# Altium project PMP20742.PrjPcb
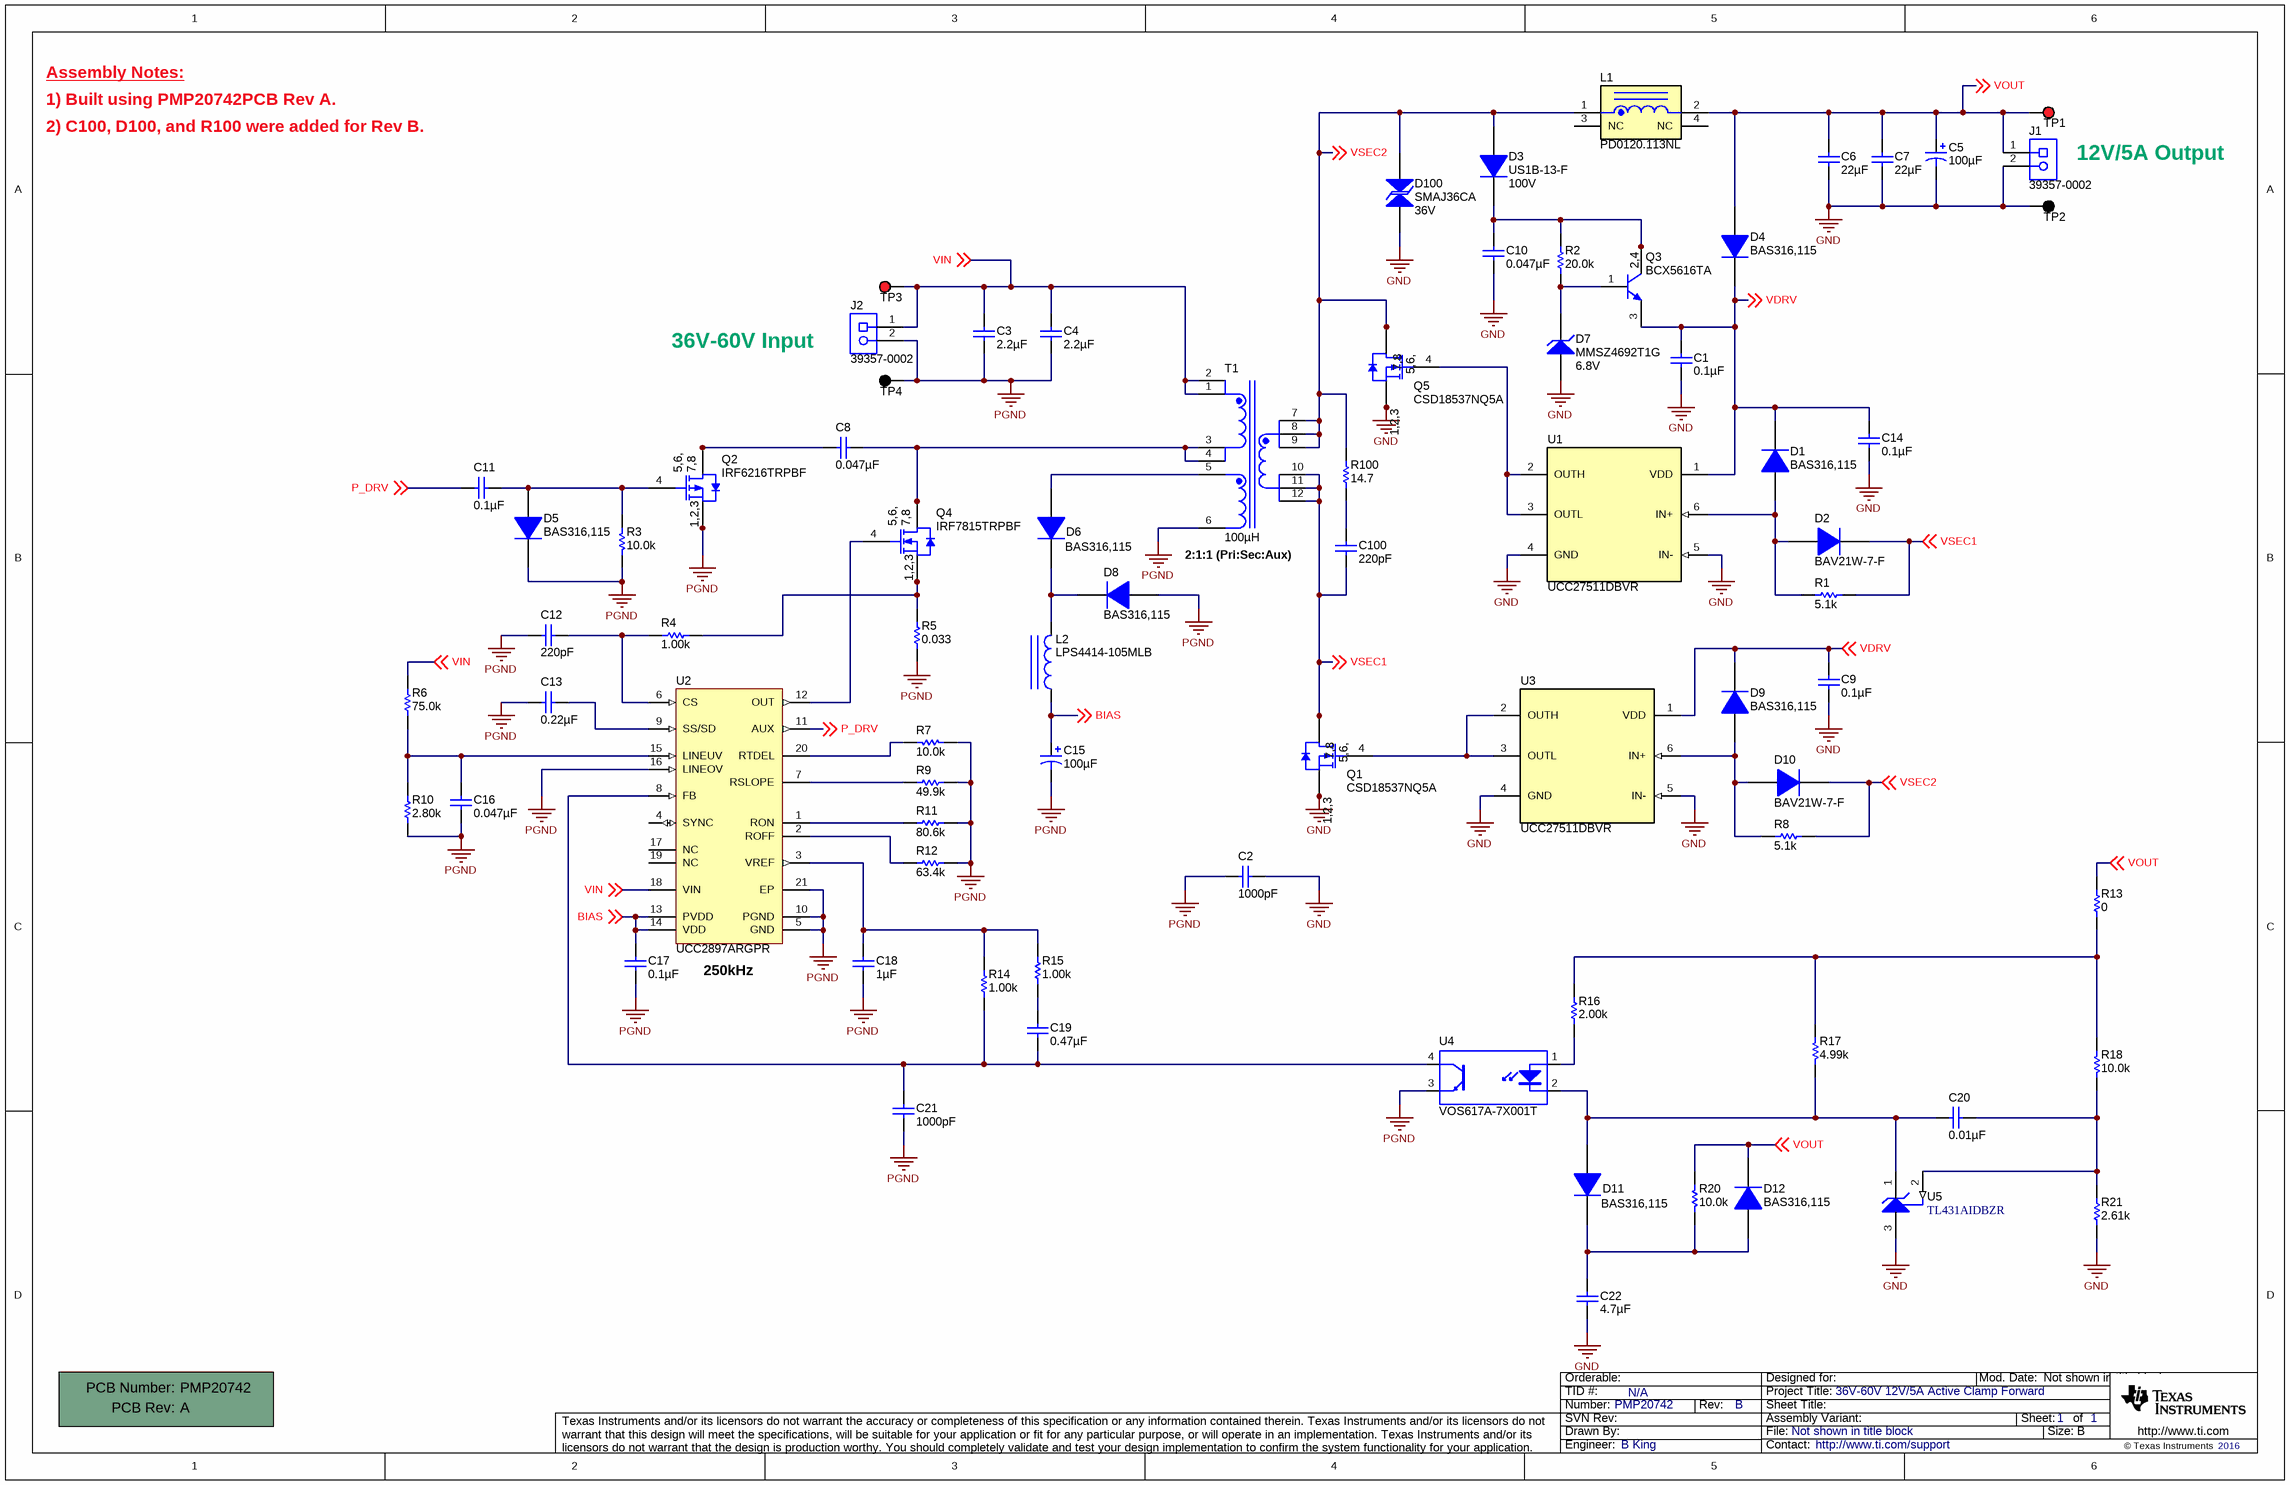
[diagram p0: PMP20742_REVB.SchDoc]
TID: N/A; TechSupport: http://www.ti.com/support; SCH_Rev: B; PRJ_Title: 36V-60V 12V/5A Active Clamp Forward; PRJ_Number: PMP20742; PRJ_Engineer: B King; PCB_Rev: A; PCB_Layout: B King; CopyrightYear: 2016
1 sheet, 77 parts. Net scope: global (net labels, ports and power ports of the same name join across sheets).
Board file: PMP20742_REVA.PcbDoc

## Sheet PMP20742_REVB.SchDoc
size 431 x 279 mm; Date: Not shown in title block; ApprovedBy: Not shown in title block; CheckedBy: Not shown in title block; Author: Not shown in title block; CompanyName: Not shown in title block; Engineer: Not shown in title block; Organization: Not shown in title block; Address1: Not shown in title block; Address2: Not shown in title block; Address3: Not shown in title block; Address4: Not shown in title block; DocumentNumber: 1; Revision: Use project parameter SCH_Rev; SheetNumber: 1; SheetTotal: 1; PageSetup: Record=PageOptions¦CenterHorizontal=True¦CenterVertical=True¦PrintScale=1.00¦XCorrection=1.00¦YCorrection=1.00¦PrintKind=0¦BorderSize=5000000¦LeftOffset=0¦BottomOffset=0¦Orientation=2¦PaperLength=1000¦PaperWidth=1000¦Scale=100¦PaperSource=15¦PrintQuality=600¦MediaType=1¦DitherType=10¦PaperKind=Letter¦PrintScaleMode=1

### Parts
!PCB1  Printed Circuit Board  (value not drawn)  (mechanical)
C1  ValueDisplayed: 0.1µF  [0402L]  (hidden comment: GRM155R71E104KE14D)
C2  ValueDisplayed: 1000pF  [1808_L]  (hidden comment: STD)
C3  ValueDisplayed: 2.2µF  [1210_270L]  (hidden comment: GRM32ER72A225KA35L)
C4  ValueDisplayed: 2.2µF  [1210_270L]  (hidden comment: GRM32ER72A225KA35L)
C5  ValueDisplayed: 100µF  [SM_RADIAL_6.3BMM]  (hidden comment: EEHZA1E101XP)
C6  ValueDisplayed: 22µF  [1206_190L]  (hidden comment: GRM31CC81E226ME11L)
C7  ValueDisplayed: 22µF  [1206_190L]  (hidden comment: GRM31CC81E226ME11L)
C8  ValueDisplayed: 0.047µF  [1206_180L]  (hidden comment: GRM31CR72E473KW03L)
C9  ValueDisplayed: 0.1µF  [0402L]  (hidden comment: GRM155R71E104KE14D)
C10  ValueDisplayed: 0.047µF  [0805L]  (hidden comment: GRM21BR72A473KA01L)
C11  ValueDisplayed: 0.1µF  [0402L]  (hidden comment: GRM155R71E104KE14D)
C12  ValueDisplayed: 220pF  [0402L]  (hidden comment: GRM1555C1H221JA01D)
C13  ValueDisplayed: 0.22µF  [0402L]  (hidden comment: GRM155R61A224KE19D)
C14  ValueDisplayed: 0.1µF  [0402L]  (hidden comment: GRM155R71E104KE14D)
C15  ValueDisplayed: 100µF  [SM_RADIAL_6.3BMM]  (hidden comment: EEHZA1E101XP)
C16  ValueDisplayed: 0.047µF  [0402L]  (hidden comment: GRM155R71E473KA88D)
C17  ValueDisplayed: 0.1µF  [0402L]  (hidden comment: GRM155R71E104KE14D)
C18  ValueDisplayed: 1µF  [0402L]  (hidden comment: GRM155R61A105KE15D)
C19  ValueDisplayed: 0.47µF  [0402L]  (hidden comment: GRM155R61C474KE01)
C20  ValueDisplayed: 0.01µF  [0402L]  (hidden comment: GRM155R71E103KA01D)
C21  ValueDisplayed: 1000pF  [0402L]  (hidden comment: GRM155R61H102KA01D)
C22  ValueDisplayed: 4.7µF  [0805L]  (hidden comment: GRM21BR71E475KA73L)
C100  ValueDisplayed: 220pF  [0603L]  (hidden comment: GRM188R72A221KA01D)
D1  BAS316,115  [sod-323]
D2  BAV21W-7-F  [SOD-123]
D3  US1B-13-F  value 100V  [SMA]
D4  BAS316,115  [sod-323]
D5  BAS316,115  [sod-323]
D6  BAS316,115  [sod-323]
D7  MMSZ4692T1G  value 6.8V  [SOD-123]
D8  BAS316,115  [sod-323]
D9  BAS316,115  [sod-323]
D10  BAV21W-7-F  [SOD-123]
D11  BAS316,115  [sod-323]
D12  BAS316,115  [sod-323]
D100  SMAJ36CA  value 36V  [SMA]
J1  39357-0002  [Molex_39357-0002]
J2  39357-0002  [Molex_39357-0002]
L1  PD0120.113NL  [PD0120NL]
L2  LPS4414-105MLB  [LPS4414]
Q1  CSD18537NQ5A  [DQJ0008A]
Q2  IRF6216TRPBF  [SOIC-8L]
Q3  BCX5616TA  [SOT-89-3]
Q4  IRF7815TRPBF  [SO-8L]
Q5  CSD18537NQ5A  [DQJ0008A]
R1  value 5.1k  [0805L]  (hidden comment: CRCW08055K10JNEA)
R2  value 20.0k  [0805L]  (hidden comment: CRCW080520K0FKEA)
R3  value 10.0k  [0402L]  (hidden comment: CRCW040210K0FKED)
R4  value 1.00k  [0402L]  (hidden comment: CRCW04021K00FKED)
R5  ValueDisplayed: 0.033  [1206L]  (hidden comment: ERJ-8CWFR033V)
R6  ValueDisplayed: 75.0k  [0402L]  (hidden comment: CRCW040275K0FKED)
R7  value 10.0k  [0402L]  (hidden comment: CRCW040210K0FKED)
R8  value 5.1k  [0805L]  (hidden comment: CRCW08055K10JNEA)
R9  ValueDisplayed: 49.9k  [0402L]  (hidden comment: CRCW040249K9FKED)
R10  ValueDisplayed: 2.80k  [0402L]  (hidden comment: CRCW04022K80FKED)
R11  ValueDisplayed: 80.6k  [0402L]  (hidden comment: CRCW040280K6FKED)
R12  ValueDisplayed: 63.4k  [0402L]  (hidden comment: CRCW040263K4FKED)
R13  value 0  [0402L]  (hidden comment: CRCW04020000Z0ED)
R14  value 1.00k  [0402L]  (hidden comment: CRCW04021K00FKED)
R15  value 1.00k  [0402L]  (hidden comment: CRCW04021K00FKED)
R16  value 2.00k  [0402L]  (hidden comment: CRCW04022K00FKED)
R17  value 4.99k  [0402L]  (hidden comment: CRCW04024K99FKED)
R18  value 10.0k  [0402L]  (hidden comment: CRCW040210K0FKED)
R20  value 10.0k  [0402L]  (hidden comment: CRCW040210K0FKED)
R21  value 2.61k  [0402L]  (hidden comment: CRCW04022K61FKED)
R100  ValueDisplayed: 14.7  [1206L]  (hidden comment: CRCW120614R7FKEA)
T1  ValueDisplayed: 100µH  [Pulse_PA2398NL]  (hidden comment: PA2398NL)
TP1  5000  [Keystone5000]  (value not drawn)
TP2  5001  [Keystone5001]  (value not drawn)
TP3  5000  [Keystone5000]  (value not drawn)
TP4  5001  [Keystone5001]  (value not drawn)
U1  UCC27511DBVR  [DBV0006A_L]
U2  UCC2897ARGPR  [RGP0020D]
U3  UCC27511DBVR  [DBV0006A_L]
U4  VOS617A-7X001T  [SSOP-4_VISHAY]
U5  TL431AIDBZR  [DBZ0003A_L]

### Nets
GND: C1.2 C2.1 C5.2(-) C6.2 C7.2 C9.2 C10.2 C14.2 C22.2 D7.2(A) D100.1 J1.2 Q1.1(S) Q1.2(S) Q1.3(S) Q5.1(S) Q5.2(S) Q5.3(S) R21.1 TP2.1 U1.4(GND) U1.5(IN-) U3.4(GND) U3.5(IN-) U5.3(ANODE)
PGND: C2.2 C3.2 C4.2 C12.1 C13.1 C15.2(-) C16.1 C17.2 C18.2 C21.2 D5.1(K) D8.2(A) J2.2 Q2.1(S) Q2.2(S) Q2.3(S) R3.1 R5.1 R7.1 R9.1 R10.1 R11.1 R12.1 T1.6 TP4.1 U2.5(GND) U2.10(PGND) U2.16(LINEOV) U2.21(EP) U4.3(E)
BIAS: C15.1(+) C17.1 L2.1 U2.13(PVDD) U2.14(VDD) ; off-sheet BIAS
P_DRV: C11.1 U2.11(AUX) ; off-sheet P_DRV
VDRV: C1.1 C9.1 C14.1 D1.1(K) D4.1(K) D9.1(K) Q3.3(E) U1.1(VDD) U3.1(VDD) ; off-sheet VDRV
VIN: C3.1 C4.1 J2.1 R6.2 T1.1 T1.2 TP3.1 U2.18(VIN) ; off-sheet VIN
VOUT: C5.1(+) C6.1 C7.1 D4.2(A) D12.1(K) J1.1 L1.2 R13.2 R20.2 TP1.1 ; off-sheet VOUT
VSEC1: C100.2 D2.1(K) Q1.5(D) Q1.6(D) Q1.7(D) Q1.8(D) Q1.9(D) R1.1 T1.10 T1.11 T1.12 ; off-sheet VSEC1
VSEC2: D3.2(A) D10.1(K) D100.2 L1.1 Q5.5(D) Q5.6(D) Q5.7(D) Q5.8(D) Q5.9(D) R8.1 R100.2 T1.7 T1.8 T1.9 ; off-sheet VSEC2
NetC8_1: C8.1 Q2.5(D) Q2.6(D) Q2.7(D) Q2.8(D)
NetC8_2: C8.2 Q4.5(D) Q4.6(D) Q4.7(D) Q4.8(D) T1.3 T1.4
NetC10_1: C10.1 D3.1(K) Q3.2(C) Q3.4(C) R2.2
NetC11_2: C11.2 D5.2(A) Q2.4(G) R3.2
NetC12_2: C12.2 R4.2 U2.6(CS)
NetC13_2: C13.2 U2.9(SS/SD)
NetC16_2: C16.2 R6.1 R10.2 U2.15(LINEUV)
NetC18_1: C18.1 R14.1 R15.1 U2.3(VREF)
NetC19_1: C19.1 R15.2
NetC19_2: C19.2 C21.1 R14.2 U2.8(FB) U4.4(C)
NetC20_1: C20.1 R18.1 R21.2 U5.2(REF)
NetC20_2: C20.2 D11.2(A) R17.1 U4.2(K) U5.1(CATHODE)
NetC22_1: C22.1 D11.1(K) D12.2(A) R20.1
NetC100_1: C100.1 R100.1
NetD1_2: D1.2(A) D2.2(A) R1.2 U1.6(IN+)
NetD6_1: D6.1(K) D8.1(K) L2.2
NetD6_2: D6.2(A) T1.5
NetD7_1: D7.1(K) Q3.1(B) R2.1
NetD9_2: D9.2(A) D10.2(A) R8.2 U3.6(IN+)
NetQ1_4: Q1.4(G) U3.2(OUTH) U3.3(OUTL)
NetQ4_1: Q4.1(S) Q4.2(S) Q4.3(S) R4.1 R5.2
NetQ4_4: Q4.4(G) U2.12(OUT)
NetQ5_4: Q5.4(G) U1.2(OUTH) U1.3(OUTL)
NetR7_2: R7.2 U2.20(RTDEL)
NetR9_2: R9.2 U2.7(RSLOPE)
NetR11_2: R11.2 U2.1(RON)
NetR12_2: R12.2 U2.2(ROFF)
NetR13_1: R13.1 R16.2 R17.2 R18.2
NetR16_1: R16.1 U4.1(A)

Not connected (* = marked no-connect by the designer): L1 3(NC) 4(NC); U2 4(SYNC) 17(NC) 19(NC)

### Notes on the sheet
- Assembly Notes:
- 1) Built using PMP20742PCB Rev A.
- 2) C100, D100, and R100 were added for Rev B.
- 12V/5A Output
- 36V-60V Input
- (near T1) 2:1:1 (Pri:Sec:Aux)
- (near U2) 250kHz

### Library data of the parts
!PCB1 = PCB: Manufacturer: Any; PartNumber: PMP20742; SymbolCreator: a0412235
C1 C9 C11 C14 C17 = GRM155R71E104KE14D: CAP, CERM, 0.1 µF, 25 V, +/- 10%, X7R, 0402; Manufacturer: MuRata; Polarized: N; CompType: Capacitor; Value: 0.1uF; U/M: EA; Cap_F: 0.0000001; Tolerance_%: 10; Value1: Unknown; VDC_V: 25; Value2: 25V; TaMin_C: -55; TaMax_C: 125; Cap_Case: 0402; SizeArea_mm2: 0.5; SizeAreaWB_mm2: 3; SizeX_mm: 1; SizeZ_mm: 0.6; AEC Category: Q200
C2 = VJ1808Y102KXEAT5Z: CAP, CERM, 1000pF, 3kV, 1808; Polarized: N; CompType: Capacitor; U/M: EA; Cap_F: 0.000000001; Tolerance_%: 10; Value1: Unknown; TempCo: X7R; TaMin_C: -55; TaMax_C: 125; Cap_Case: 1808
C3 C4 = GRM32ER72A225KA35L: CAP, CERM, 2.2 µF, 100 V, +/- 10%, X7R, 1210; Manufacturer: MuRata; Polarized: N; CompType: Capacitor; Value: 2.2uF; U/M: EA; Cap_F: 0.0000022; Tolerance_%: 10; ESR_ohm: 0.007; Value1: 0.007 ohm; VDC_V: 100; Value2: 100V; IRMS_A: 4.4; TaMin_C: -55; TaMax_C: 125; Cap_Case: 1210; SizeArea_mm2: 8; SizeAreaWB_mm2: 14.7; SizeX_mm: 3.2; SizeY_mm: 2.5; SizeZ_mm: 2.7; AEC Category: Q200
C5 C15 = EEHZA1E101XP: CAP, Polymer Hybrid, 100 µF, 25 V, +/- 20%, 30 ohm, 6.3x7.7 SMD; Manufacturer: Panasonic; Polarized: Y; CompType: Capacitor; Value: 100uF; U/M: EA; Cap_F: 0.0001; Tolerance_%: 20; Value1: 30 ohm; VDC_V: 25; Value2: 25V; ESR_ohm: 30; IRMS_A: 2; TaMin_C: -55; TaMax_C: 105; SizeAreaWB_mm2: 79.98; SizeArea_mm2: 48.18; SizeX_mm: 7.3; SizeY_mm: 6.6; SizeZ_mm: 7.7; AEC Category: Q200
C6 C7 = GRM31CC81E226ME11L: CAP, CERM, 22 µF, 25 V, +/- 20%, X6S, 1206_190; Manufacturer: MuRata; Polarized: N; CompType: Capacitor; Value: 22uF; U/M: EA; Cap_F: 0.000022; Tolerance_%: 20; Value1: Unknown; VDC_V: 25; Value2: 25V; TaMin_C: -55; TaMax_C: 105; Cap_Case: 1206; SizeArea_mm2: 5.12; SizeAreaWB_mm2: 10.92; SizeX_mm: 3.2; SizeY_mm: 1.6; SizeZ_mm: 1.9; AEC Category: Q200
C8 = GRM31CR72E473KW03L: CAP, CERM, 0.047 µF, 250 V, +/- 10%, X7R, 1206; Manufacturer: MuRata; Polarized: N; CompType: Capacitor; Value: 0.047uF; U/M: EA; Cap_F: 0.000000047; Tolerance_%: 10; Value1: Unknown; VDC_V: 250; Value2: 250V; TaMin_C: -55; TaMax_C: 125; Cap_Case: 1206; SizeArea_mm2: 5.12; SizeAreaWB_mm2: 10.92; SizeX_mm: 3.2; SizeY_mm: 1.6; SizeZ_mm: 1.8; AEC Category: Q200
C10 = GRM21BR72A473KA01L: CAP, CERM, 0.047 µF, 100 V, +/- 10%, X7R, 0805; Manufacturer: MuRata; Polarized: N; CompType: Capacitor; Value: 0.047uF; U/M: EA; Cap_F: 0.000000047; Tolerance_%: 10; Value1: Unknown; VDC_V: 100; Value2: 100V; TaMin_C: -55; TaMax_C: 125; Cap_Case: 0805; SizeArea_mm2: 2.5; SizeAreaWB_mm2: 6.75; SizeX_mm: 2; SizeY_mm: 1.25; SizeZ_mm: 1.45; AEC Category: Q200
C12 = GRM1555C1H221JA01D: CAP, CERM, 220 pF, 50 V, +/- 5%, C0G/NP0, 0402; Manufacturer: MuRata; Polarized: N; CompType: Capacitor; Value: 220pF; U/M: EA; Cap_F: 0.00000000022; Tolerance_%: 5; Value1: Unknown; VDC_V: 50; Value2: 50V; TaMin_C: -55; TaMax_C: 125; Cap_Case: 0402; SizeArea_mm2: 0.5; SizeAreaWB_mm2: 3; SizeX_mm: 1; SizeZ_mm: 0.6; AEC Category: Q200
C13 = GRM155R61A224KE19D: CAP, CERM, 0.22uF, 10V, +/-10%, X5R, 0402; Manufacturer: MuRata; Polarized: N; CompType: Capacitor; U/M: EA; Cap_F: 0.00000022; Tolerance_%: 10; Value1: Unknown; TaMin_C: -55; TaMax_C: 85; Cap_Case: 0402
C16 = GRM155R71E473KA88D: CAP, CERM, 0.047uF, 25V, +/-10%, X7R, 0402; Manufacturer: MuRata; Polarized: N; CompType: Capacitor; U/M: EA; Cap_F: 0.000000047; Tolerance_%: 10; Value1: Unknown; VDC_V: 25; TaMin_C: -55; TaMax_C: 125; Cap_Case: 0402
C18 = GRM155R61A105KE15D: CAP, CERM, 1uF, 10V, +/-10%, X5R, 0402; Manufacturer: MuRata; Polarized: N; CompType: Capacitor; U/M: EA; Cap_F: 0.000001; Tolerance_%: 10; Value1: Unknown; TaMin_C: -55; TaMax_C: 85; Cap_Case: 0402
C19 = GRM155R61C474KE01: CAP, CERM, 0.47 µF, 16 V, +/- 10%, X5R, 0402; Manufacturer: MuRata; Polarized: N; CompType: Capacitor; Value: 0.47uF; U/M: EA; Cap_F: 0.00000047; Tolerance_%: 10; Value1: Unknown; VDC_V: 16; Value2: 16V; TaMin_C: -55; TaMax_C: 85; Cap_Case: 0402; SizeArea_mm2: 0.5; SizeAreaWB_mm2: 3; SizeX_mm: 1; SizeZ_mm: 0.6; AEC Category: Q200
C20 = GRM155R71E103KA01D: CAP, CERM, 0.01 µF, 25 V, +/- 10%, X7R, 0402; Manufacturer: MuRata; Polarized: N; CompType: Capacitor; Value: 0.01uF; U/M: EA; Cap_F: 0.00000001; Tolerance_%: 10; Value1: Unknown; VDC_V: 25; Value2: 25V; TaMin_C: -55; TaMax_C: 125; Cap_Case: 0402; SizeArea_mm2: 0.5; SizeAreaWB_mm2: 3; SizeX_mm: 1; SizeZ_mm: 0.6; AEC Category: Q200
C21 = GRM155R61H102KA01D: CAP, CERM, 1000 pF, 50 V, +/- 10%, X5R, 0402; Manufacturer: MuRata; Polarized: N; CompType: Capacitor; Value: 1000pF; U/M: EA; Cap_F: 0.000000001; Tolerance_%: 10; Value1: Unknown; VDC_V: 50; Value2: 50V; TaMin_C: -55; TaMax_C: 85; Cap_Case: 0402; SizeArea_mm2: 0.5; SizeAreaWB_mm2: 3; SizeX_mm: 1; SizeZ_mm: 0.6; AEC Category: Q200
C22 = GRM21BR71E475KA73L: CAP, CERM, 4.7 µF, 25 V, +/- 10%, X7R, 0805; Manufacturer: MuRata; Polarized: N; CompType: Capacitor; Value: 4.7uF; U/M: EA; Cap_F: 0.0000047; Tolerance_%: 10; Value1: Unknown; VDC_V: 25; Value2: 25V; TaMin_C: -55; TaMax_C: 125; Cap_Case: 0805; SizeArea_mm2: 2.5; SizeAreaWB_mm2: 6.75; SizeX_mm: 2; SizeY_mm: 1.25; SizeZ_mm: 1.45; AEC Category: Q200
C100 = GRM188R72A221KA01D: CAP, CERM, 220 pF, 100 V, +/- 10%, X7R, 0603; Manufacturer: MuRata; Polarized: N; CompType: Capacitor; Value: 220pF; U/M: EA; Cap_F: 0.00000000022; Tolerance_%: 10; Value1: Unknown; VDC_V: 100; Value2: 100V; TaMin_C: -55; TaMax_C: 125; Cap_Case: 0603; SizeArea_mm2: 1.28; SizeAreaWB_mm2: 4.68; SizeX_mm: 1.6; SizeY_mm: 0.8; SizeZ_mm: 1; AEC Category: Q200
D1 D4 D9 = BAS316,115: Diode, Ultrafast, 100V, 0.25A, SOD-323; Manufacturer: NXP Semiconductor; U/M: EA; Vf_V: 1.4; Io_A: 0.25; Vr_V: 100; Value2: 1.4V; TJmax_C: 150
D2 D10 = BAV21W-7-F: Diode, Switching, 200V, 0.2A, SOD-123; Manufacturer: Diodes Inc.; Value: 1.25V; U/M: EA; Vf_V: 1.25; Io_A: 0.2; Vr_V: 200; TJmax_C: 150
D3 = US1B-13-F: Diode, Ultrafast, 100V, 1A, SMA; Manufacturer: Diodes Inc.; U/M: EA; Vf_V: 1; Vr_V: 100; Value2: 1V; TJmax_C: 150; RJC_CperW: 30
D5 D6 D8 D11 D12 = BAS316,115: Diode, Ultrafast, 100V, 0.25A, SOD-323; Manufacturer: NXP Semiconductor; Value: 1.4V; U/M: EA; Vf_V: 1.4; Io_A: 0.25; Vr_V: 100; TJmax_C: 150
D7 = MMSZ4692T1G: Diode, Zener, 6.8 V, 500 mW, SOD-123; Manufacturer: ON Semiconductor; SymbolCreator: a0412235; U/M: EA; Power_W: 0.5; Vz_V: 6.8; Value1: 0.5W; RJA_CperW: 340; SizeAreaWB_mm2: 13.095; SizeArea_mm2: 6.545; SizeX_mm: 3.85; SizeY_mm: 1.7; SizeZ_mm: 1.35; AEC Category: Q101
D100 = SMAJ36CA: Diode, TVS, Bi, 36 V, SMA; Manufacturer: Littelfuse; U/M: EA; Power_W: 3.3; Vr_V: 36; Value1: 3.3W; RJA_CperW: 120; SizeAreaWB_mm2: 37.3428; SizeArea_mm2: 16.3228; SizeX_mm: 5.59; SizeY_mm: 2.92; SizeZ_mm: 2.87; AEC Category: Q101
J1 J2 = 39357-0002: Terminal Block, 3.5 mm, 2x1, Tin, TH; Manufacturer: Molex; SymbolCreator: a0412235
L1 = PD0120.113NL: Inductor, Wirewound, 7.6 A, 0.016 ohm, SMD; Manufacturer: Pulse Engineering; SymbolCreator: Altium; Imax_A: 7.6; Irms: 7.6A @ 45C rise; Isat: 9A @ 10% inductance drop; DCR_ohm: 0.016; Value2: 7.6A; SizeAreaWB_mm2: 326.69; SizeArea_mm2: 258.39; SizeX_mm: 15.95; SizeY_mm: 16.2; SizeZ_mm: 8.2; AEC Category: Q200; AEC Qualified: N
L2 = LPS4414-105MLB: Inductor, Shielded Drum Core, Ferrite, 1mH, 0.11A, 16.3 ohm, SMD; Manufacturer: Coilcraft; Ind_H: 1.0E-3; Imax_A: 0.11; Irms: 0.13A @ 40C rise; Isat: 0.106A @ 30% inductance drop; DCR_ohm: 16.3; U/M: EA
Q1 Q5 = CSD18537NQ5A: MOSFET, N-CH, 60 V, 50 A, DQJ0008A (VSONP-8); Manufacturer: Texas Instruments; Alternate Manufacturer: None; U/M: EA; ChType: N; Value: 60V; VdsMax_V: 60; Value1: 0.036 ohm; Rdson45_ohm: 0.036; Value2: 14 nC; QgTyp_nC: 14; Vgs_V: 20; IdsMax_A: 50; SizeAreaWB_mm2: 55.2; SizeArea_mm2: 29.4; SizeX_mm: 6; SizeY_mm: 4.9; SizeZ_mm: 1.1; AEC Category: Q101
Q2 = IRF6216TRPBF: MOSFET, P-CH, -150 V, -2.2 A, SOIC-8; Manufacturer: International Rectifier; Alternate Manufacturer: None; U/M: EA; ChType: P; Value: -150V; Value1: ? ohm; Value2: 15 nC; QgTyp_nC: 15; Vgs_V: -20; SizeAreaWB_mm2: 55.131; SizeArea_mm2: 29.351; SizeX_mm: 5.99; SizeY_mm: 4.9; SizeZ_mm: 1.75; AEC Category: Q101; AEC Qualified: N
Q3 = BCX5616TA, Diodes Inc.: Transistor, NPN, 80V, 1A, SOT-89; CompType: BJT; PNP: 0; NPN: 1; Vceo_V: 80; Vcesat1_V: 0.5; Value: 0.5V; HfeMax: 250; TaMin_C: -65; TaMax_C: 150; U/M: EA
Q4 = IRF7815TRPBF: MOSFET, N-CH, 150 V, 5.1 A, SO-8; Manufacturer: Infineon Technologies; Alternate Manufacturer: None; U/M: EA; ChType: N; Value: 150V; VdsMax_V: 150; Value1: ? ohm; Value2: 25 nC; QgTyp_nC: 25; Vgs_V: 20; IdsMax_A: 5.1; AEC Category: Q101
R1 R8 = CRCW08055K10JNEA: RES, 5.1k ohm, 5%, 0.125W, 0805; Manufacturer: Vishay-Dale; CompType: Resistor; Res_ohm: 5100; Value_Code: 5k10; Tolerance_%: 5; Power_W: 0.125; VDC_V: 150; TempCo: 200 ppm/C; EIA_Code: E24; U/M: EA
R2 = CRCW080520K0FKEA: RES, 20.0k ohm, 1%, 0.125W, 0805; Manufacturer: Vishay-Dale; CompType: Resistor; Res_ohm: 20000; Value_Code: 20k0; Tolerance_%: 1; Power_W: 0.125; VDC_V: 150; TempCo: 100 ppm/C; EIA_Code: E96; U/M: EA
R3 R7 R18 R20 = CRCW040210K0FKED: RES, 10.0k ohm, 1%, 0.063W, 0402; Manufacturer: Vishay-Dale; CompType: Resistor; Res_ohm: 10000; Value_Code: 10k0; Tolerance_%: 1; Power_W: 0.063; VDC_V: 50; TempCo: 100 ppm/C; EIA_Code: E96; U/M: EA
R4 R14 R15 = CRCW04021K00FKED: RES, 1.00k ohm, 1%, 0.063W, 0402; Manufacturer: Vishay-Dale; CompType: Resistor; Res_ohm: 1000; Value_Code: 1k00; Tolerance_%: 1; Power_W: 0.063; VDC_V: 50; TempCo: 100 ppm/C; EIA_Code: E96; U/M: EA
R5 = ERJ-8CWFR033V: RES, 0.033, 1%, 1 W, AEC-Q200 Grade 0, 1206; Manufacturer: Panasonic; CompType: Resistor; Value: 0.033; Value_Code: R033; Tolerance_%: 1; Value2: 1W; TempCo: 50 ppm/C; SizeArea_mm2: 5.12; SizeX_mm: 3.2; SizeY_mm: 1.6; SizeZ_mm: 1.35; EIA_Code: E96; U/M: EA; AEC Category: Q200; AEC Qualified: Y; AEC Grade: 0
R6 = CRCW040275K0FKED: RES, 75.0 k, 1%, 0.063 W, 0402; Manufacturer: Vishay-Dale; CompType: Resistor; Value: 75.0k; Res_ohm: 75000; Value_Code: 75k0; Tolerance_%: 1; Power_W: 0.063; Value2: 0.063W; VDC_V: 50; TempCo: 100 ppm/C; EIA_Code: E96; U/M: EA; SizeArea_mm2: 0.5; SizeZ_mm: 0.6; AEC Category: Q200
R9 = CRCW040249K9FKED: RES, 49.9 k, 1%, 0.063 W, 0402; Manufacturer: Vishay-Dale; CompType: Resistor; Value: 49.9k; Res_ohm: 49900; Value_Code: 49k9; Tolerance_%: 1; Power_W: 0.063; Value2: 0.063W; VDC_V: 50; TempCo: 100 ppm/C; EIA_Code: E96; U/M: EA; SizeArea_mm2: 0.5; SizeZ_mm: 0.6; AEC Category: Q200
R10 = CRCW04022K80FKED: RES, 2.80 k, 1%, 0.063 W, 0402; Manufacturer: Vishay-Dale; CompType: Resistor; Value: 2.80k; Res_ohm: 2800; Value_Code: 2k80; Tolerance_%: 1; Power_W: 0.063; Value2: 0.063W; VDC_V: 50; TempCo: 100 ppm/C; EIA_Code: E96; U/M: EA; SizeArea_mm2: 0.5; SizeZ_mm: 0.6; AEC Category: Q200
R11 = CRCW040280K6FKED: RES, 80.6 k, 1%, 0.063 W, 0402; Manufacturer: Vishay-Dale; CompType: Resistor; Value: 80.6k; Res_ohm: 80600; Value_Code: 80k6; Tolerance_%: 1; Power_W: 0.063; Value2: 0.063W; VDC_V: 50; TempCo: 100 ppm/C; EIA_Code: E96; U/M: EA; SizeArea_mm2: 0.5; SizeZ_mm: 0.6; AEC Category: Q200
R12 = CRCW040263K4FKED: RES, 63.4 k, 1%, 0.063 W, 0402; Manufacturer: Vishay-Dale; CompType: Resistor; Value: 63.4k; Res_ohm: 63400; Value_Code: 63k4; Tolerance_%: 1; Power_W: 0.063; Value2: 0.063W; VDC_V: 50; TempCo: 100 ppm/C; EIA_Code: E96; U/M: EA; SizeArea_mm2: 0.5; SizeZ_mm: 0.6; AEC Category: Q200
R13 = CRCW04020000Z0ED: RES, 0 ohm, 5%, 0.063W, 0402; Manufacturer: Vishay-Dale; CompType: Resistor; Value_Code: 0000; Tolerance_%: 5; Power_W: 0.063; VDC_V: 50; TempCo: 200 ppm/C; EIA_Code: E24; U/M: EA
R16 = CRCW04022K00FKED: RES, 2.00k ohm, 1%, 0.063W, 0402; Manufacturer: Vishay-Dale; CompType: Resistor; Res_ohm: 2000; Value_Code: 2k00; Tolerance_%: 1; Power_W: 0.063; VDC_V: 50; TempCo: 100 ppm/C; EIA_Code: E96; U/M: EA
R17 = CRCW04024K99FKED: RES, 4.99k ohm, 1%, 0.063W, 0402; Manufacturer: Vishay-Dale; CompType: Resistor; Res_ohm: 4990; Value_Code: 4k99; Tolerance_%: 1; Power_W: 0.063; VDC_V: 50; TempCo: 100 ppm/C; EIA_Code: E96; U/M: EA
R21 = CRCW04022K61FKED: RES, 2.61k ohm, 1%, 0.063W, 0402; Manufacturer: Vishay-Dale; CompType: Resistor; Res_ohm: 2610; Value_Code: 2k61; Tolerance_%: 1; Power_W: 0.063; VDC_V: 50; TempCo: 100 ppm/C; EIA_Code: E96; U/M: EA
R100 = CRCW120614R7FKEA: RES, 14.7, 1%, 0.25 W, 1206; Manufacturer: Vishay-Dale; CompType: Resistor; Value: 14.7; Value_Code: 14R7; Tolerance_%: 1; Power_W: 0.25; Value2: 0.25W; VDC_V: 200; TempCo: 100 ppm/C; SizeArea_mm2: 5.12; SizeX_mm: 3.2; SizeY_mm: 1.6; SizeZ_mm: 1.35; EIA_Code: E96; U/M: EA; AEC Category: Q200
T1 = PA2398NL: Transformer, 100 uH, SMT; Manufacturer: Pulse Engineering; SymbolCreator: Altium; Value: 100uH; Lp: 100; DCR_ohm: 0.072; LeakageL: 0.45; Rs1: 0.015; SizeAreaWB_mm2: 744.0464; SizeArea_mm2: 637.9464; SizeX_mm: 29.21; SizeY_mm: 21.84; SizeZ_mm: 11.43
TP1 TP3 = 5000: Test Point, Miniature, Red, TH; Manufacturer: Keystone; CompType: Test Point Loop; ContactFinish: Silver
TP2 TP4 = 5001: Test Point, Miniature, Black, TH; Manufacturer: Keystone; CompType: Test Point Loop; ContactFinish: Silver
U1 U3 = UCC27511DBVR: Single-Channel High-Speed Low-Side Gate Driver (with 4-A Peak Source and 8-A Peak Sink), DBV0006A (SOT-6); Alternate PartNumber: UCC27511DBVT; Manufacturer: Texas Instruments; SymbolCreator: a0411947; SizeArea_mm2: 8.12; SizeAreaWB_mm2: 14.82; SizeX_mm: 2.8; SizeY_mm: 2.9; SizeZ_mm: 1.45; CompType: IC; U/M: EA
U2 = UCC2897ARGPR: Advanced Active Clamp PWM Controller with Current Control, -40 to +125 degC, 20-pin QFN (RGP), Green (RoHS & no Sb/Br); Manufacturer: Texas Instruments; Alternate Manufacturer: None; Alternate PartNumber: Equivalent; Frequency(Max)(kHz): 1000; Rating: Catalog; Regulated Outputs(#): 1
U4 = VOS617A-7X001T: OptoCoupler, Phototransitor, 80-160%, SSOP-4; Manufacturer: Vishay-Semiconductor; U/M: EA
U5 = TL431AIDBZR: Adjustable Precision Shunt Regulator, 34 ppm / degC, 100 mA, -40 to 85 degC, 3-pin SOT-23 (DBZ), Green (RoHS & no Sb/Br); Manufacturer: Texas Instruments; Alternate PartNumber: Equivalent; Initial Accuracy @ 25/deg C(%): 1; Iout/Iz(Max)(mA): 100; Min Iz for Regulation(uA): 600; Rating: Catalog; SubFamily: Shunt Voltage Reference; Temp Coeff(Max)(ppm/ degree C): 92; Temp Coeff(Typ)(ppm/ degree C): 34; VO Adj(Max)(V): 36; VO Adj(Min)(V): 2.495

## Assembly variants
001: all parts fitted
